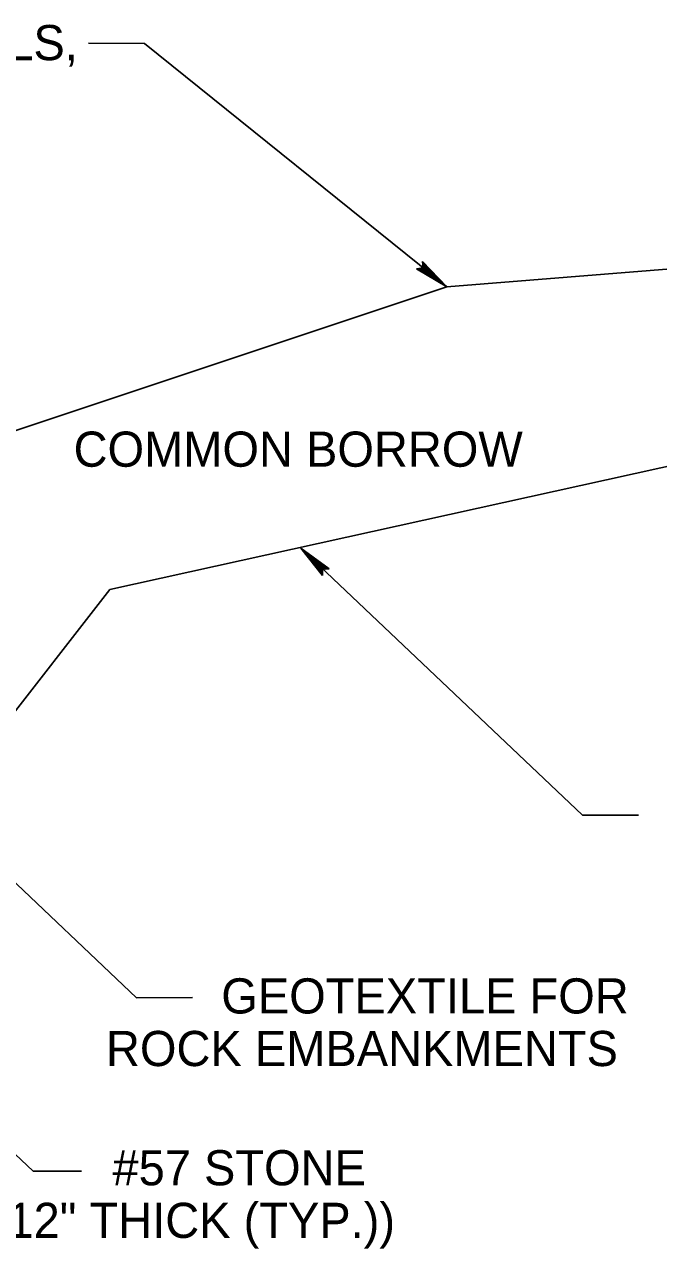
# Model space of a CAD drawing. Extents: x 2189223 to 2190097, y 563994 to 564498.
# Drawn here: x 2189546.8 to 2189594.6, y 564106.5 to 564198.6 of the extents above; entities that cross this region are included whole.
import ezdxf

# ---------------------------------------------------------------- set-up
doc = ezdxf.new("R2010")
doc.units = 0
for name, color, linetype in [('Default', 7, 'Continuous'), ('Exist XS Ground Line', 7, 'Continuous'), ('Old_Level_2', 7, 'Continuous')]:
    doc.layers.add(name, color=color, linetype=linetype)

msp = doc.modelspace()

# ---------------------------------------------------------------- linework, layer by layer
at = {"layer": 'Default'}
for p, q in [((2189555.858, 564197.178), (2189551.653, 564197.198)), ((2189578.615, 564178.866), (2189555.858, 564197.178)), ((2189567.64, 564159.191), (2189588.831, 564139.088)), ((2189534.079, 564145.455), (2189555.27, 564125.352)), ((2189516.848, 564141.001), (2189547.495, 564112.312)), ((2189588.831, 564139.088), (2189593.036, 564139.108)), ((2189555.27, 564125.352), (2189559.475, 564125.372)), ((2189547.495, 564112.312), (2189551.138, 564112.312))]:
    msp.add_line(p, q, dxfattribs=at)
for points in [[(2189621.101, 564182.265), (2189578.615, 564178.866)], [(2189578.615, 564178.866), (2189478.962, 564145.652)]]:
    msp.add_lwpolyline(points, dxfattribs=at)
at = {"layer": 'Exist XS Ground Line'}
for p, q in [((2189553.259, 564156.073), (2189634.447, 564174.016)), ((2189523.562, 564117.949), (2189553.259, 564156.073))]:
    msp.add_line(p, q, dxfattribs=at)
at = {"layer": 'Old_Level_2'}
for p, q in [((2189578.615, 564178.866), (2189576.783, 564180.76)), ((2189576.83, 564180.277), (2189576.783, 564180.76)), ((2189578.615, 564178.866), (2189576.789, 564180.692)), ((2189576.8, 564180.623), (2189578.615, 564178.866)), ((2189578.615, 564178.866), (2189576.805, 564180.555)), ((2189576.812, 564180.481), (2189578.615, 564178.866)), ((2189578.615, 564178.866), (2189576.815, 564180.415)), ((2189576.347, 564180.207), (2189576.83, 564180.277)), ((2189578.615, 564178.866), (2189576.347, 564180.207)), ((2189576.415, 564180.218), (2189578.615, 564178.866)), ((2189578.615, 564178.866), (2189576.485, 564180.226)), ((2189576.554, 564180.236), (2189578.615, 564178.866)), ((2189578.615, 564178.866), (2189576.626, 564180.247)), ((2189576.69, 564180.257), (2189578.615, 564178.866)), ((2189578.615, 564178.866), (2189576.761, 564180.265)), ((2189576.823, 564180.344), (2189578.615, 564178.866)), ((2189576.83, 564180.277), (2189578.615, 564178.866)), ((2189567.64, 564159.191), (2189569.762, 564157.63)), ((2189567.64, 564159.191), (2189569.273, 564157.123)), ((2189569.274, 564157.192), (2189567.64, 564159.191)), ((2189567.64, 564159.191), (2189569.272, 564157.263)), ((2189569.274, 564157.332), (2189567.64, 564159.191)), ((2189567.64, 564159.191), (2189569.275, 564157.405)), ((2189569.275, 564157.47), (2189567.64, 564159.191)), ((2189567.64, 564159.191), (2189569.274, 564157.541)), ((2189569.277, 564157.611), (2189567.64, 564159.191)), ((2189569.344, 564157.613), (2189567.64, 564159.191)), ((2189567.64, 564159.191), (2189569.415, 564157.615)), ((2189569.482, 564157.62), (2189567.64, 564159.191)), ((2189567.64, 564159.191), (2189569.556, 564157.624)), ((2189569.624, 564157.627), (2189567.64, 564159.191)), ((2189567.64, 564159.191), (2189569.693, 564157.626)), ((2189569.273, 564157.123), (2189569.277, 564157.611)), ((2189569.277, 564157.611), (2189569.762, 564157.63))]:
    msp.add_line(p, q, dxfattribs=at)

# ---------------------------------------------------------------- texts
at = {"layer": 'Default'}
for s, height, p in [('FOR ROADWAY DETAILS,', 2.64588, (2189507.407, 564195.912)), ('COMMON BORROW', 2.64588, (2189550.532, 564165.317)), ('GEOTEXTILE FOR ', 2.64588, (2189561.646, 564124.172)), ('ROCK EMBANKMENTS', 2.64588, (2189552.968, 564120.214)), ('#57 STONE ', 2.6459, (2189553.46, 564111.24)), ('(12" THICK (TYP.))', 2.64588, (2189544.376, 564107.282))]:
    msp.add_text(s, height=height, dxfattribs=at).set_placement(p)

doc.saveas('drawing.dxf')
